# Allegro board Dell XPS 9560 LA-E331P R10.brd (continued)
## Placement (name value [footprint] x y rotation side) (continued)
PJP600  -  [JUMP_43X118]  279.59 30.74 180 bottom
PJP601  PAD-OPEN1X1M  [JUMP_43X39]  283.15 30.43 0 bottom
PJP602  PAD-OPEN 3X3M  [JUMP_43X79]  283.02 28.9 270 top
PJP603  PAD-OPEN 4X4M  [JUMP_43X118]  256.73 25.2 270 bottom
PJP700  PAD-OPEN 3X3M  [JUMP_43X79]  185.7 115.9 0 top
PJP701  PAD-OPEN 4X4M  [JUMP_43X118]  215.71 117.65 270 top
PJP702  PAD-OPEN 4X4M  [JUMP_43X118]  215.71 117.65 270 bottom
PJP800  -  [JUMP_43X118]  117.22 63.83 0 bottom
PJP900  -  [JUMP_43X118]  224.28 116.09 180 bottom
PJP1200  -  [JUMP_43X118]  129.21 107.13 90 bottom
PJP1205  PAD-OPEN1X1M  [JUMP_43X39]  307.73 21.92 180 top
PJP1206  PAD-OPEN1X1M  [JUMP_43X39]  276.28 8.64 0 top
PJP1300  -  [JUMP_43X118]  107.25 68.59 270 top
PJP1301  -  [JUMP_43X118]  109.28 98.24 90 bottom
PJP1302  PAD-OPEN 43X39  [JUMP_43X39]  103.07 17.92 180 top
PJP1303  PAD-OPEN 43X39  [JUMP_43X39]  102.95 13.6 180 top
PL104  BLM15AG102SN1D_2P  [MURAT_BLM15AG102SN1D_2P]  17.83 75.76 0 top
PL105  HCB2012KF-121T50_0805  [TAI-T_HCB2012KF-121T50_2P]  26.54 77.03 0 bottom
PL106  HCB2012KF-121T50_0805  [TAI-T_HCB2012KF-121T50_2P]  27.1 78.62 90 bottom
PL107  HCB2012KF-121T50_0805  [TAI-T_HCB2012KF-121T50_2P]  23.37 22.23 270 bottom
PL108  HCB2012KF-121T50_0805  [TAI-T_HCB2012KF-121T50_2P]  21.59 22.23 270 bottom
PL200  HCB2012KF-121T50_0805  [TAI-T_HCB2012KF-121T50_2P]  21.72 23.82 0 top
PL201  HCB2012KF-121T50_0805  [TAI-T_HCB2012KF-121T50_2P]  21.72 22.17 0 top
PL202  HCB2012KF-121T50_0805  [TAI-T_HCB2012KF-121T50_2P]  21.44 18.85 270 top
PL203  HCB2012KF-121T50_0805  [TAI-T_HCB2012KF-121T50_2P]  19.39 18.81 270 top
PL300  HCB2012KF-121T50_0805  [TAI-T_HCB2012KF-121T50_2P]  52.44 9.72 180 bottom
PL301  HCB2012KF-121T50_0805  [TAI-T_HCB2012KF-121T50_2P]  52.44 8.01 180 bottom
PL302  3.3UH_VMPI1004AR-3R3M-Z01_11A_20%  [TAI-T_VMPI1004AR-3R3M-Z01_2P]  35.99 3.97 90 bottom
PL400  3.3UH_PCMB063T-3R3MS_6.5A_20%  [CYNTE_PCMB063T-3R3MS_2P]  331.37 25.32 0 top
PL401  1.5UH_PCMC063T-1R5MN_9A_20%  [CYNTE_PCMC063T-1R5MN_2P]  336.13 6.1 180 top
PL402  HCB2012KF-121T50_0805  [TAI-T_HCB2012KF-121T50_2P]  318.26 14.42 0 top
PL403  HCB2012KF-121T50_0805  [TAI-T_HCB2012KF-121T50_2P]  318.26 16.2 0 top
PL500  HCB2012KF-121T50_0805  [TAI-T_HCB2012KF-121T50_2P]  136.83 10.61 180 bottom
PL501  1UH_PCMB053T-1R0MS_7A_20%  [CYNTE_PCMB053T-1R0MS_2P]  128.78 3.88 180 bottom
PL600  1UH_PCMB063T-1R0MS_12A_20%  [CYNTE_PCMB063T-1R0MS_2P]  262.53 31.76 0 bottom
PL601  HCB2012KF-121T50_0805  [TAI-T_HCB2012KF-121T50_2P]  279.39 27.31 180 bottom
PL700  HCB2012KF-121T50_0805  [TAI-T_HCB2012KF-121T50_2P]  185.25 118.69 0 bottom
PL701  0.47UH_MMD-06CZ-R47M-V1_17.5A_20%  [MAG_MMD-06CZ-R47M-V1_2P]  198.95 115.64 0 bottom
PL800  HCB2012KF-121T50_0805  [TAI-T_HCB2012KF-121T50_2P]  105.09 57.49 90 top
PL801  1UH_PCMB053T-1R0MS_7A_20%  [CYNTE_PCMB053T-1R0MS_2P]  112.9 60.52 90 bottom
PL900  HCB2012KF-121T50_0805  [TAI-T_HCB2012KF-121T50_2P]  246.37 114.82 180 bottom
PL901  1UH_PCMB053T-1R0MS_7A_20%  [CYNTE_PCMB053T-1R0MS_2P]  235.79 114.69 180 bottom
PL1000  HCB2012KF-121T50_0805  [TAI-T_HCB2012KF-121T50_2P]  163.32 108.51 270 bottom
PL1001  HCB2012KF-121T50_0805  [TAI-T_HCB2012KF-121T50_2P]  165.04 108.5 270 bottom
PL1002  0.22UH_MMD-06DZIR22MEM2L_32A_20%  [MAG_MMD-06DZIR22MEM2L_2P]  176.17 99.96 0 bottom
PL1003  0.22UH_MMD-06DZIR22MEM2L_32A_20%  [MAG_MMD-06DZIR22MEM2L_2P]  176.86 107.13 0 bottom
PL1200  0.22UH_MMD-06DZIR22MEM2L_32A_20%  [MAG_MMD-06DZIR22MEM2L_2P]  146.46 105.04 0 bottom
PL1201  0.22UH_MMD-06DZIR22MEM2L_32A_20%  [MAG_MMD-06DZIR22MEM2L_2P]  146.46 112.53 0 bottom
PL1202  0.22UH_MMD-06DZIR22MEM2L_32A_20%  [MAG_MMD-06DZIR22MEM2L_2P]  158.24 108.67 270 bottom
PL1203  HCB2012KF-121T50_0805  [TAI-T_HCB2012KF-121T50_2P]  134.54 106.88 90 bottom
PL1204  HCB2012KF-121T50_0805  [TAI-T_HCB2012KF-121T50_2P]  132.83 106.88 90 bottom
PL1300  0.22UH_MMD-06DZIR22MEM2L_32A_20%  [MAG_MMD-06DZIR22MEM2L_2P]  112.99 82.36 0 bottom
PL1301  0.22UH_MMD-06DZIR22MEM2L_32A_20%  [MAG_MMD-06DZIR22MEM2L_2P]  112.12 70.24 0 bottom
PL1303  HCB2012KF-121T50_0805  [TAI-T_HCB2012KF-121T50_2P]  106.62 67.06 90 bottom
PL1304  HCB2012KF-121T50_0805  [TAI-T_HCB2012KF-121T50_2P]  108.4 67.06 90 bottom
PL1305  HCB2012KF-121T50_0805  [TAI-T_HCB2012KF-121T50_2P]  105.6 97.42 270 bottom
PL1306  0.47UH_MMD05CZR47M_12A_20%  [MAG_MMD05CZR47M_4P]  108.4 88.77 0 bottom
PL1400  1UH_1239AS-H-1R0M-P2_3A_20%  [TOKO_1239AS-H-1R0M-P2_2P]  247.41 104.28 0 top
PL1444  HCB2012KF-121T50_0805  [TAI-T_HCB2012KF-121T50_2P]  248.41 112.32 270 top
PL1500  0.22UH_MMD-06DZIR22MEM2L_32A_20%  [MAG_MMD-06DZIR22MEM2L_2P]  190.63 100.18 0 bottom
PL1501  HCB2012KF-121T50_0805  [TAI-T_HCB2012KF-121T50_2P]  183.07 112.9 270 top
PL1502  HCB2012KF-121T50_0805  [TAI-T_HCB2012KF-121T50_2P]  184.79 112.9 270 top
PQ100  -  [FDV301N-G_SOT23-3]  42.74 33.98 180 top
PQ101  -  [MMBT3904WH_SOT323-3]  39.03 32.77 270 top
PQ200  -  [AON7409_DFN8-5]  20.89 27.59 90 bottom
PQ201  -  [AON7409_DFN8-5]  28.58 29.6 270 bottom
PQ204  -  [NTR4502PT1G_SOT23-3]  16.1 33.85 270 top
PQ205  S TR 2N7002KW 1N SOT323-3  [SSM3K7002FU_SC70-3]  26.17 32.58 270 top
PQ206  S TR 2N7002KW 1N SOT323-3  [SSM3K7002FU_SC70-3]  30.1 33.53 180 top
PQ208  S TR 2N7002KW 1N SOT323-3  [SSM3K7002FU_SC70-3]  22.74 28.47 270 top
PQ211  S TR 2N7002KW 1N SOT323-3  [SSM3K7002FU_SC70-3]  22.74 30.86 270 top
PQ212  -  [AON7409_DFN8-5]  13.11 29.8 0 bottom
PQ213  -  [AON7409_DFN8-5]  18.77 26.93 180 bottom
PQ214  -  [AON7409_DFN8-5]  15.54 63.28 180 bottom
PQ216  -  [NTR4502PT1G_SOT23-3]  14.48 27.15 0 top
PQ217  -  [NTR4502PT1G_SOT23-3]  20.92 7.73 270 top
PQ218  S TR 2N7002KW 1N SOT323-3  [SSM3K7002FU_SC70-3]  16.7 59.7 180 bottom
PQ219  S TR 2N7002KW 1N SOT323-3  [SSM3K7002FU_SC70-3]  25.85 4.33 270 top
PQ220  S TR 2N7002KW 1N SOT323-3  [SSM3K7002FU_SC70-3]  25.83 1.92 270 top
PQ221  -  [AO3413_SOT23-3]  36.32 24.88 0 top
PQ222  S TR 2N7002KW 1N SOT323-3  [SSM3K7002FU_SC70-3]  30.1 1.6 0 top
PQ223  S TR 2N7002KW 1N SOT323-3  [SSM3K7002FU_SC70-3]  15.69 1.66 0 top
PQ224  -  [AO3413_SOT23-3]  14.48 22.42 0 top
PQ225  S TR 2N7002KW 1N SOT323-3  [SSM3K7002FU_SC70-3]  27.75 26.08 90 top
PQ228  S TR 2N7002KW 1N SOT323-3  [SSM3K7002FU_SC70-3]  11.11 24.2 270 bottom
PQ229  S TR 2N7002KW 1N SOT323-3  [SSM3K7002FU_SC70-3]  22.99 13.79 180 top
PQ230  S TR 2N7002KW 1N SOT323-3  [SSM3K7002FU_SC70-3]  6.16 18.93 90 bottom
PQ231  S TR 2N7002KW 1N SOT323-3  [SSM3K7002FU_SC70-3]  33.4 31.5 180 top
PQ232  S TR 2N7002KW 1N SOT323-3  [SSM3K7002FU_SC70-3]  30.35 7.33 180 top
PQ233  S TR 2N7002KW 1N SOT323-3  [SSM3K7002FU_SC70-3]  20.26 13.79 180 top
PQ300  -  [SIR472DP-T1-GE3_POWERPAK8-5]  43.18 13.88 90 bottom
PQ301  -  [SIR472DP-T1-GE3_POWERPAK8-5]  42.51 8.02 90 bottom
PQ302  -  [SIRA06DP-T1-GE_POWERPAKSO-8-5]  47.68 5.98 270 bottom
PQ303  -  [AON7409_DFN8-5]  28.13 22.16 270 bottom
PQ304  S TR 2N7002KW 1N SOT323-3  [SSM3K7002FU_SC70-3]  57.42 11.11 180 bottom
PQ400  -  [MDV1528URH_PDFN33-8-5]  332.42 21.15 180 top
PQ401  -  [MDU1516URH_POWERDFN56-8-5]  326.9 10.64 0 top
PQ402  -  [MDV1524URH_PDFN33-8-5]  334.58 18.11 0 top
PQ403  -  [MDU1512RH_POWERDFN56-8-5]  337.25 15.99 180 top
PQ600  -  [AON7406L_DFN8-5]  271.19 30.91 90 bottom
PQ601  -  [AON7516_DFN8-5]  273.57 28.29 270 bottom
PQ700  -  [RJU003N03_UMT3]  198.57 110.66 0 top
PQ1300  -  [AON7934_DFN3X3A8-10]  107.13 92.46 90 bottom
PR100  0_0402_5%  [R_0402]  45.15 33.68 270 top
PR101  2.2K_0402_1%  [R_0402]  45.15 30.98 90 top
PR102  33_0402_5%  [R_0402]  18.75 74.85 180 top
PR103  100K_0402_1%  [R_0402]  40.34 34.45 180 top
PR104  10K_0402_1%  [R_0402]  40.26 31.43 90 top
PR105  15K_0402_1%  [R_0402]  38.5 34.45 180 top
PR106  100_0402_1%  [R_0402]  19.88 10.12 270 top
PR108  100_0402_1%  [R_0402]  21.27 14.09 90 top
PR111  100_0402_1%  [R_0402]  26 11.88 0 top
PR112  10K_0402_1%  [R_0402]  26.92 13.09 180 top
PR200  100K_0402_5%  [R_0402]  27.42 28.94 270 top
PR201  1M_0402_5%  [R_0402]  20.7 29.04 270 top
PR202  100K_0402_5%  [R_0402]  18.09 31.38 0 top
PR203  100K_0402_5%  [R_0402]  26.51 28.03 90 top
PR205  1M_0402_5%  [R_0402]  21.59 28.13 90 top
PR206  100K_0402_5%  [R_0402]  27.14 34.21 0 top
PR209  0_0402_5%  [R_0402]  26.61 29.78 90 top
PR213  1M_0402_5%  [R_0402]  20.63 30.22 90 top
PR217  1M_0402_5%  [R_0402]  22.43 29.92 180 top
PR219  1M_0402_5%  [R_0402]  11.75 61.08 90 top
PR220  100K_0402_5%  [R_0402]  21.48 3.3 90 top
PR222  1M_0402_5%  [R_0402]  21.48 2.47 270 top
PR223  100K_0402_5%  [R_0402]  25.08 8.71 270 top
PR224  1M_0402_5%  [R_0402]  23.13 10.17 180 top
PR225  1M_0402_5%  [R_0402]  14.78 59.32 0 bottom
PR226  100K_0402_5%  [R_0402]  20.92 5.15 0 top
PR227  0_0402_5%  [R_0402]  16.63 26.21 0 top
PR228  0_0402_5%  [R_0402]  26.67 7.45 270 top
PR229  100K_0402_5%  [R_0402]  20.08 4.07 180 top
PR230  100K_0402_5%  [R_0402]  25.08 6.93 270 top
PR231  100K_0402_1%  [R_0402]  18.3 3.5 180 top
PR232  10K_0402_1%  [R_0402]  24.08 1.81 90 top
PR234  100K_0402_5%  [R_0402]  13.13 2.42 0 top
PR235  0_0402_5%  [R_0402]  28.66 7.76 270 top
PR240  100K_0402_5%  [R_0402]  17.35 21.66 180 top
PR243  100K_0402_5%  [R_0402]  16.96 23.45 270 top
PR251  100K_0402_1%  [R_0402]  9.44 21.6 0 bottom
PR252  100K_0402_1%  [R_0402]  9.46 22.72 0 top
PR253  100K_0402_1%  [R_0402]  9.46 22.49 0 bottom
PR254  180K_0402_1%  [R_0402]  15.36 22.88 0 bottom
PR255  100K_0402_1%  [R_0402]  18.59 22.88 180 bottom
PR257  180K_0402_1%  [R_0402]  10.38 23.97 180 top
PR258  1.8M_0402_1%  [R_0402]  17.34 21.01 90 bottom
PR259  1.8M_0402_1%  [R_0402]  11.81 22.75 270 top
PR260  130K_0402_1%  [R_0402]  19.51 19.06 180 bottom
PR261  140K_0402_1%  [R_0402]  9.4 18.61 0 bottom
PR263  16.5K_0402_1%  [R_0402]  10.33 21.85 180 top
PR264  200K_0402_1%  [R_0402]  9.46 24.85 0 top
PR265  200K_0402_1%  [R_0402]  13.53 22.88 0 bottom
PR267  0_0402_5%  [R_0402]  24.07 4.66 270 top
PR268  0_0402_5%  [R_0402]  30.81 29.33 90 top
PR270  1M_0402_5%  [R_0402]  11.23 3.82 0 top
PR271  300K_0402_5%  [R_0402]  28.31 24.58 0 top
PR272  300K_0402_5%  [R_0402]  28.31 23.69 0 top
PR273  16.5K_0402_1%  [R_0402]  17.65 20.07 0 bottom
PR275  100K_0402_1%  [R_0402]  34.28 31.94 0 top
PR276  2K_0402_1%  [R_0402]  35.15 33.78 180 top
PR277  0_0402_5%  [R_0402]  31.75 31.39 270 top
PR278  100K_0402_1%  [R_0402]  18.61 11.87 90 top
PR279  0_0402_5%  [R_0402]  19.24 14.09 90 top
PR281  0_0402_5%  [R_0402]  12 23.75 90 top
PR282  100K_0402_5%  [R_0402]  13.13 1.53 0 top
PR283  100K_0402_5%  [R_0402]  9.08 2.16 90 top
PR290  0_0402_5%  [R_0402]  8.45 11.17 90 bottom
PR300  0.01_1206_1%  [R_1206_4P-D]  55.02 8.26 270 bottom
PR301  0_0402_5%  [R_0402]  52.57 11.1 90 top
PR302  0_0402_5%  [R_0402]  51.69 11.1 90 top
PR303  4.02K_0402_1%  [R_0402]  54.17 11.76 90 top
PR304  10_1206_5%  [R_1206]  51.12 15.06 270 bottom
PR305  294K_0402_1%  [R_0402]  55.77 12.67 270 bottom
PR306  0_0402_5%  [R0402_0OHM]  60.26 17.48 180 top
PR307  2.2_0603_5%  [R_0603]  50.8 17.53 180 top
PR308  59K_0402_1%  [R_0402]  55.88 14.28 90 bottom
PR309  0_0402_5%  [R0402_0OHM]  60.26 18.37 180 top
PR310  0.005_2512_1%  [RL-3264-9W-R005-FNH_2512_2512]  38.33 23.02 90 bottom
PR311  100K_0402_1%  [R_0402]  54.9 11.76 90 bottom
PR312  0_0402_5%  [R0402_0OHM]  54.04 11.76 90 bottom
PR313  4.7_1206_5%  [R_1206]  32.58 3.88 90 top
PR314  0_0402_5%  [R0402_0OHM]  56.9 11.76 90 top
PR315  100_0402_1%  [R_0402]  60.26 16.52 180 top
PR316  150K_0402_1%  [R_0402]  55.12 12.65 270 top
PR317  0_0402_5%  [R0402_0OHM]  60.28 14.74 180 top
PR318  10K_0402_1%  [R_0402]  52.39 21.34 90 top
PR319  4.02K_0402_1%  [R_0402]  55.18 21.22 90 top
PR320  10_0603_1%  [R_0603]  56.26 21.22 90 bottom
PR321  1K_0402_1%  [R_0402]  57.34 22.42 270 top
PR322  0_0402_5%  [R0402_0OHM]  58.23 22.42 270 top
PR323  121K_0402_1%  [R_0402]  56.83 19.45 270 bottom
PR324  0_0402_5%  [R0402_0OHM]  60.28 15.63 180 top
PR325  10K_0402_1%  [R_0402]  57.8 16.52 180 bottom
PR326  2.2K_0402_5%  [R_0402]  346.97 26.3 270 top
PR327  100K_0402_5%  [R_0402]  58.93 10.63 270 bottom
PR399  0_0402_5%  [R_0402]  52.77 11.74 90 bottom
PR400  0_0402_5%  [R0402_0OHM]  348.88 21.98 180 bottom
PR401  68.1K_0402_1%  [R_0402]  348.87 22.87 180 top
PR402  160K_0402_1%  [R_0402]  348.03 18.93 0 top
PR403  100K_0402_1%  [R_0402]  348.87 21.98 180 top
PR404  102K_0402_1%  [R_0402]  348.03 19.82 0 top
PR405  16.9K_0402_1%  [R_0402]  346.97 24.41 270 top
PR406  10.2K_0402_1%  [R_0402]  348.03 18.04 0 top
PR407  0_0402_5%  [R0402_0OHM]  345.12 24.41 270 top
PR408  0_0402_5%  [R0402_0OHM]  346.08 24.41 270 top
PR409  0_0402_5%  [R0402_0OHM]  347.98 17.14 90 bottom
PR410  200_0402_1%  [R_0402]  348.03 17.09 0 top
PR411  2.2_0603_5%  [R_0603]  342.27 24.08 0 top
PR412  2.2_0603_5%  [R_0603]  341.89 17.22 0 top
PR413  4.7_1206_5%  [R_1206]  337.25 31.17 180 top
PR414  4.7_1206_5%  [R_1206]  339.28 10.68 90 top
PR415  0_0402_5%  [R0402_0OHM]  340.58 21.97 180 top
PR428  100K_0402_1%  [R_0402]  345.12 24.41 270 bottom
PR500  0_0402_5%  [R0402_0OHM]  131.03 3.2 270 bottom
PR501  1M_0402_1%  [R_0402]  130.68 3.18 270 top
PR502  4.7_1206_5%  [R_1206]  126.68 8.33 0 bottom
PR503  0_0603_5%  [R_0603]  134.88 7.69 180 top
PR504  90.9K_0402_1%  [R_0402]  134.76 2.16 90 top
PR508  133K_0402_1%  [R_0402]  135.68 3.06 270 top
PR510  0_0402_5%  [R_0402]  132.46 2.26 90 top
PR512  0_0402_5%  [R_0402]  133.33 2.97 270 bottom
PR600  2.2_0603_5%  [R_0603]  283.15 28.65 0 bottom
PR601  3.57K_0402_1%  [R_0402]  288.99 26.49 180 bottom
PR602  4.7_1206_5%  [R_1206]  269.43 26.87 180 bottom
PR603  5.1_0603_5%  [R_0603]  289.54 25.23 90 top
PR604  16.2K_0402_1%  [R_0402]  291.85 31.19 90 top
PR605  1M_0402_1%  [R_0402]  292.75 27.19 180 bottom
PR606  0_0402_5%  [R0402_0OHM]  292.75 28.46 180 bottom
PR607  27K_0402_1%  [R_0402]  292.8 31.19 90 bottom
PR608  0_0402_5%  [R0402_0OHM]  292.75 29.35 180 bottom
PR609  100K_0402_5%  [R_0402]  291.92 27 180 top
PR610  0_0402_5%  [R_0402]  291.83 30.23 0 top
PR700  0_0402_5%  [R0402_0OHM]  187.17 118.53 0 top
PR701  187K_0402_1%  [R_0402]  191.52 118.96 270 bottom
PR702  107K_0402_1%  [R_0402]  190.56 118.96 270 bottom
PR703  200K_0402_1%  [R_0402]  189.61 118.96 270 bottom
PR704  19.1K_0402_1%  [R_0402]  194.31 118.94 270 bottom
PR705  10_1206_5%  [R_1206]  195.26 115.58 0 top
PR706  0_0402_5%  [R0402_0OHM]  194.88 118.96 270 top
PR707  100K_0402_1%  [R_0402]  196.85 118.97 270 top
PR708  2_0603_5%  [R_0603]  196.72 113.99 270 top
PR722  23.2K_0402_1%  [R_0402]  193.36 118.94 270 bottom
PR724  95.3K_0402_1%  [R_0402]  196.79 110.83 270 top
PR725  100K_0402_5%  [R_0402]  199.4 107.9 180 top
PR728  0_0402_5%  [R0402_0OHM]  199.4 106.88 180 top
PR729  10_0402_1%  [R_0402]  192.28 118.96 270 top
PR730  0_0402_5%  [R0402_0OHM]  193.36 118.04 90 top
PR755  2.7K_0402_1%  [R_0402]  197.89 117.04 0 top
PR800  0_0402_5%  [R0402_0OHM]  109.92 64.51 90 bottom
PR801  1M_0402_1%  [R_0402]  109.03 64.51 90 bottom
PR802  4.7_1206_5%  [R_1206]  114.17 57.67 180 bottom
PR803  0_0603_5%  [R_0603]  107.19 62.11 270 top
PR804  36.5K_0402_1%  [R_0402]  107.13 64.51 90 bottom
PR806  62K_0402_1%  [R_0402]  105.28 64.51 90 top
PR808  0_0402_5%  [R_0402]  171.69 70.68 270 top
PR809  0_0402_5%  [R_0402]  170.74 70.68 270 top
PR810  100_0402_1%  [R_0402]  170.74 72.46 270 top
PR811  0_0402_5%  [R_0402]  108.08 65.43 270 bottom
PR812  0_0402_5%  [R_0402]  107.13 64.51 90 top
PR813  100_0402_1%  [R_0402]  171.69 72.46 270 top
PR902  1M_0402_1%  [R_0402]  240.48 110.55 90 top
PR903  4.7_1206_5%  [R_1206]  232.67 115.01 0 top
PR904  0_0603_5%  [R_0603]  241.68 114.25 180 top
PR905  100K_0402_1%  [R_0402]  245.3 110.17 180 bottom
PR906  10K_0402_5%  [R_0402]  241.36 110.55 90 bottom
PR907  133K_0402_1%  [R_0402]  243.14 111.46 270 bottom
PR908  0_0402_5%  [R_0402]  241.36 110.55 90 top
PR909  0_0402_5%  [R_0402]  242.25 110.56 90 top
PR910  0_0402_5%  [R_0402]  242.25 111.46 270 bottom
PR986  0_0402_5%  [R_0402]  241.38 109.29 180 top
PR987  0_0402_5%  [R_0402]  241.38 108.42 180 top
PR988  62K_0402_1%  [R_0402]  241.38 107.54 180 top
PR1000  10K_0402_1%  [R_0402]  163.95 116.4 0 bottom
PR1001  22.6K_0402_1%  [R_0402]  165.18 115.39 180 bottom
PR1002  169K_0402_1%  [R_0402]  166.55 115.51 0 top
PR1003  0_0402_5%  [R0402_0OHM]  163.91 117.41 0 bottom
PR1004  2.2K_0402_5%  [R_0402]  165.18 114.44 180 bottom
PR1005  20.5K_0402_1%  [R_0402]  167.39 117.99 90 top
PR1006  4.32K_0402_1%  [R_0402]  167.32 118.06 90 bottom
PR1007  6.19K_0402_1%  [R_0402]  166.37 118.97 270 bottom
PR1008  16.5K_0402_1%  [R_0402]  168.59 117.87 90 bottom
PR1009  10_1206_5%  [R_1206]  176.98 98.62 180 top
PR1010  2.2_0603_5%  [R_0603]  164.58 112.47 180 bottom
PR1011  309_0402_1%  [R_0402]  172.2 115.32 0 bottom
PR1012  2.2_0603_5%  [R_0603]  167.53 110.75 180 bottom
PR1013  412K_0402_1%  [R_0402]  170.5 118.91 270 bottom
PR1014  20_0402_1%  [R_0402]  171.45 117.99 90 bottom
PR1015  2.2_0603_5%  [R_0603]  171.65 112.03 0 bottom
PR1016  100_0402_1%  [R_0402]  173.61 110.87 0 top
PR1017  0_0402_5%  [R0402_0OHM]  171.71 114.05 0 top
PR1018  0_0402_5%  [R0402_0OHM]  170.32 115.71 180 top
PR1019  10K_0402_5%  [R_0402]  172.19 113.55 0 bottom
PR1020  10_1206_5%  [R_1206]  177 106.37 180 top
PR1021  0_0402_5%  [R0402_0OHM]  172.1 116.15 180 top
PR1022  82K_0402_1%  [R_0402]  172.2 114.44 0 bottom
PR1023  100_0402_1%  [R_0402]  178.64 110.89 180 top
PR1100  12.1K_0402_1%  [R_0402]  111.13 109.99 0 bottom
PR1101  1_0402_5%  [R_0402]  117.54 112.09 270 bottom
PR1102  0_0402_5%  [R0402_0OHM]  118.43 112.09 270 bottom
PR1103  100_0402_1%  [R_0402]  116.8 108.82 180 bottom
PR1104  95.3K_0402_1%  [R_0402]  111.13 109.04 0 bottom
PR1105  10.2K_0402_1%  [R_0402]  111.13 108.09 0 top
PR1106  27.4K_0402_1%  [R_0402]  108.78 107.2 0 bottom
PR1107  165K_0402_1%  [R_0402]  122.44 111.2 90 top
PR1108  16.9K_0402_1%  [R_0402]  121.55 111.2 90 top
PR1109  5.62K_0402_1%  [R_0402]  120.59 111.2 90 top
PR1110  110K_0402_1%  [R_0402]  119.7 111.2 90 top
PR1111  3.6K_0402_1%  [R_0402]  111.13 107.13 0 bottom
PR1112  1K_0402_1%  [R_0402]  108.83 106.24 0 top
PR1113  2.94K_0402_1%  [R_0402]  109.73 104.47 90 top
PR1114  1.91K_0402_1%  [R_0402]  113.92 112.09 270 top
PR1115  1.1K_0402_1%  [R_0402]  122.56 108.91 0 top
PR1116  48.7K_0402_1%  [R_0402]  123.31 110.82 0 top
PR1117  1K_0402_1%  [R_0402]  124.84 108.9 90 top
PR1118  0_0402_5%  [R0402_0OHM]  111.99 112.09 270 top
PR1119  0_0402_5%  [R0402_0OHM]  112.97 112.09 270 top
PR1120  11K_0402_1%  [R_0402]  123.41 109.91 180 bottom
PR1121  2.61K_0402_1%  [R_0402]  114.07 93.05 0 bottom
PR1122  2.61K_0402_1%  [R_0402]  120.31 86.43 0 bottom
PR1123  11K_0402_1%  [R_0402]  112.04 103.01 180 bottom
PR1124  2K_0402_1%  [R_0402]  123.05 107.13 0 top
PR1125  1K_0402_1%  [R_0402]  125.1 105.37 270 bottom
PR1126  4.42K_0402_1%  [R_0402]  122.56 105.29 0 bottom
PR1127  1K_0402_1%  [R_0402]  109.73 104.45 90 bottom
PR1128  2.49K_0402_1%  [R_0402]  122.56 106.24 0 bottom
PR1129  102K_0402_1%  [R_0402]  122.56 104.28 0 top
PR1130  412_0402_1%  [R_0402]  111.13 105.29 0 bottom
PR1131  45.3_0402_1%  [R_0402]  114.81 114 270 top
PR1132  0_0402_5%  [R0402_0OHM]  115.76 112.1 270 top
PR1133  357_0402_1%  [R_0402]  118.49 100.47 270 bottom
PR1134  11K_0402_1%  [R_0402]  119.86 98.28 270 bottom
PR1135  1K_0402_1%  [R_0402]  118.11 97.24 90 bottom
PR1136  2.61K_0402_1%  [R_0402]  150.11 99.89 180 bottom
PR1137  90.9K_0402_1%  [R_0402]  112.9 100.47 270 top
PR1138  27.4K_0402_1%  [R_0402]  113.67 98.69 0 top
PR1139  2K_0402_1%  [R_0402]  116.59 100.47 270 top
PR1140  1K_0402_1%  [R_0402]  117.48 100.45 270 bottom
PR1141  2.26K_0402_1%  [R_0402]  115.7 100.47 270 bottom
PR1142  2.43K_0402_1%  [R_0402]  116.59 99.55 90 bottom
PR1143  2K_0402_1%  [R_0402]  109.55 107.2 180 top
PR1144  10.2K_0402_1%  [R_0402]  114.75 99.55 90 top
PR1145  100_0402_1%  [R_0402]  116.65 114 270 top
PR1200  10_1206_5%  [R_1206]  147.77 103.39 270 top
PR1201  100K_0402_1%  [R_0402]  128.27 99.77 180 bottom
PR1202  3.65K_0603_1%  [R_0603]  129.2 99.25 0 bottom
PR1203  2.2_0402_1%  [R_0402]  127.38 98.81 0 bottom
PR1204  10_1206_5%  [R_1206]  145.23 117.29 0 bottom
PR1205  100K_0402_1%  [R_0402]  128.27 101.93 180 bottom
PR1206  3.65K_0603_1%  [R_0603]  129.2 100.5 0 bottom
PR1207  2.2_0402_1%  [R_0402]  127.38 100.97 0 bottom
PR1208  10_1206_5%  [R_1206]  160.78 107.32 90 top
PR1209  100K_0402_1%  [R_0402]  128.08 97.74 180 bottom
PR1210  3.65K_0603_1%  [R_0603]  128.98 97 0 bottom
PR1211  2.2_0402_1%  [R_0402]  127.15 96.83 0 bottom
PR1212  100K_0402_1%  [R_0402]  125.73 99.77 180 bottom
PR1213  100K_0402_1%  [R_0402]  125.73 98.81 180 bottom
PR1214  100K_0402_1%  [R_0402]  125.73 101.67 180 bottom
PR1215  100K_0402_1%  [R_0402]  125.73 100.72 180 bottom
PR1216  100K_0402_1%  [R_0402]  125.68 96.66 180 bottom
PR1217  100K_0402_1%  [R_0402]  125.67 97.54 180 bottom
PR1218  0_0402_5%  [R0402_0OHM-NPM]  147.45 105.04 0 bottom
PR1219  0_0402_5%  [R0402_0OHM-NPM]  151.51 105.04 180 bottom
PR1220  0_0402_5%  [R0402_0OHM-NPM]  147.45 112.59 0 bottom
PR1221  0_0402_5%  [R0402_0OHM-NPM]  151.51 112.59 180 bottom
PR1222  0_0402_5%  [R0402_0OHM-NPM]  158.18 107.64 270 bottom
PR1223  0_0402_5%  [R0402_0OHM-NPM]  158.18 103.64 90 bottom
PR1224  2.2_0402_1%  [R_0402]  137.54 109.88 270 bottom
PR1225  2.2_0402_1%  [R_0402]  137.67 115.71 270 bottom
PR1226  2.2_0402_1%  [R_0402]  157.43 118.88 180 bottom
PR1300  4.7_1206_5%  [R_1206]  111.63 81.29 270 top
PR1301  3.65K_0603_1%  [R_0603]  105.92 101.99 90 top
PR1302  2.2_0402_1%  [R_0402]  109.22 102.83 270 top
PR1303  100K_0402_1%  [R_0402]  105.98 102.18 90 bottom
PR1304  2.2_0402_1%  [R_0402]  108.27 101.91 90 top
PR1305  3.65K_0603_1%  [R_0603]  107.19 101.99 90 top
PR1306  100K_0402_1%  [R_0402]  107.19 102.18 90 bottom
PR1307  4.7_1206_5%  [R_1206]  112.02 69.41 90 top
PR1308  4.7_1206_5%  [R_1206]  105.54 87.7 90 bottom
PR1309  3.65K_0603_1%  [R_0603]  126.62 104.21 90 top
PR1311  0_0402_5%  [R_0402]  115.46 95.51 90 top
PR1312  0_0402_5%  [R0402_0OHM-NPM]  114 82.48 0 bottom
PR1313  0_0402_5%  [R0402_0OHM-NPM]  118.06 82.48 180 bottom
PR1314  0_0402_5%  [R0402_0OHM-NPM]  113.11 70.24 0 bottom
PR1315  0_0402_5%  [R0402_0OHM-NPM]  117.18 70.24 180 bottom
PR1318  10_0402_1%  [R_0402]  116.65 112.1 270 top
PR1319  49.9_0402_1%  [R_0402]  114.81 112.1 270 top
PR1320  2.2_0402_1%  [R_0402]  103.93 81.49 270 bottom
PR1321  2.2_0402_1%  [R_0402]  103.63 77.26 270 bottom
PR1400  100K_0402_5%  [R_0402]  245.95 109.23 180 bottom
PR1401  4.7_0603_5%  [R_0603]  247.65 104.85 0 bottom
PR1402  20K_0402_1%  [R_0402]  243.07 108.34 0 bottom
PR1403  0_0402_5%  [R_0402]  244.08 103.7 0 bottom
PR1404  1M_0402_1%  [R_0402]  245 102.75 180 bottom
PR1405  10K_0402_1%  [R_0402]  244.03 107.4 270 bottom
PR1500  10K_0402_1%  [R_0402]  178.25 111.81 0 top
PR1501  0_0402_5%  [R_0402]  177.86 111.99 270 bottom
PR1502  8.2K_0402_1%  [R_0402]  178.82 111.99 270 bottom
PR1503  0_0402_5%  [R0402_0OHM]  176.65 113.42 0 bottom
PR1505  20.5K_0402_1%  [R_0402]  177.31 114.88 180 top
PR1507  6.19K_0402_1%  [R_0402]  176.65 114.31 0 bottom
PR1508  4.32K_0402_1%  [R_0402]  176.3 116.91 0 top
PR1509  16.5K_0402_1%  [R_0402]  176.32 117.86 0 bottom
PR1510  2.2_0603_5%  [R_0603]  181.8 111.45 0 bottom
PR1511  309_0402_1%  [R_0402]  177.2 116.91 180 bottom
PR1512  10_1206_5%  [R_1206]  190.18 101.42 90 top
PR1513  2.2_0603_5%  [R_0603]  182.31 118.63 0 bottom
PR1514  20_0402_1%  [R_0402]  175.22 118.45 270 bottom
PR1515  412K_0402_1%  [R_0402]  176.32 118.82 0 bottom
PR1516  100_0402_1%  [R_0402]  175.99 119.13 0 top
PR1517  0_0402_5%  [R0402_0OHM]  206.57 55.52 270 bottom
PR1518  0_0402_5%  [R0402_0OHM]  181.11 119.45 0 top
PR1519  33K_0402_1%  [R_0402]  180.18 118.75 180 bottom
PR1520  0_0402_5%  [R0402_0OHM]  207.52 55.52 270 bottom
PR1521  100_0402_1%  [R_0402]  176.01 118.12 0 top
PR1800  100K_0402_1%  [R_0402]  178.86 14.2 180 top
PR1801  0_0402_5%  [R0402_0OHM]  178.8 8.82 90 top
PR1803  21.5K_0402_1%  [R_0402]  180.75 15.22 180 top
PR1804  10K_0402_1%  [R_0402]  178.94 16.11 270 top
PR1805  0.01_0603_1%  [R_0603]  181.37 17.22 180 top
PU202  -  [LM393DMR2G_MICRO8]  16.07 21.6 270 bottom
PU203  -  [RT9069-33GB_SOT23-5]  28.63 20.34 90 top
PU204  -  [MC74VHC1G08DFT2G_SC70-5]  10.1 2.75 270 top
PU300  BQ24777ARUYR_WQFN28_4X4  [BQ24777RUYR_WQFN28_4X4]  53.91 15.06 90 top
PU400  -  [TPS51285BRUKR_QFN20_3X3]  345.95 19.5 180 top
PU500  -  [SYX196DQNC_QFN10_3X3]  131.53 4.5 0 bottom
PU600  -  [G5616ARZ1U_TQFN20_3X3]  287.47 31.12 0 bottom
PU700  -  [TPS53353DQPR_QFN22_5X6]  195.22 116.43 270 bottom
PU800  -  [SYX196DQNC_QFN10_3X3]  109.41 62.75 180 bottom
PU900  -  [SYX196DQNC_QFN10_3X3]  239.35 113.34 0 bottom
PU1000  -  [CSD86360Q5D_SON8-7]  167.93 99.73 90 bottom
PU1001  -  [RT8816AGQW_WQFN20_3X3]  166.66 113.64 90 bottom
PU1002  -  [CSD86360Q5D_SON8-7]  168.69 105.48 90 bottom
PU1100  -  [ISL95829AHRTZ-T_TQFN48_6X6]  114.17 108.09 0 top
PU1200  -  [AOZ5029QI_QFN24_5X3P5]  138.84 108.78 90 bottom
PU1201  -  [AOZ5029QI_QFN24_5X3P5]  138.9 114.4 90 bottom
PU1202  -  [AOZ5029QI_QFN24_5X3P5]  156.16 117.46 0 bottom
PU1300  -  [AOZ5029QI_QFN24_5X3P5]  105.35 80.08 90 bottom
PU1301  -  [AOZ5029QI_QFN24_5X3P5]  104.59 72.46 90 bottom
PU1302  -  [ISL95808HRZ-TS2378_DFN8_2X2]  115.73 95.45 270 bottom
PU1400  G5719CRC1U_TDFN8_2X2  [G5719CRC1U_TDFN8_2X2-S]  245.17 107.2 0 bottom
PU1501  -  [RT8816AGQW_WQFN20_3X3]  181.72 113.85 180 bottom
PU1502  -  [CSD86360Q5D_SON8-7]  188.41 109.83 0 bottom
PU1800  -  [RT9059GQW_WDFN10_3X3]  182.03 13.87 180 top
QE2  -  [DMN65D8LDW-7_SOT363-6]  196.22 10.83 0 top
QE4  -  [DMN65D8LDW-7_SOT363-6]  311.67 16.07 180 top
QE5  MMBT3904WH_SOT323-3  [MMBT3904WH_SOT323-3-S]  173.6 119.53 180 bottom
QE6  -  [MMBT3904WH_SOT323-3]  181.03 77.57 0 top
QE7  -  [MMBT3904WH_SOT323-3]  112.56 111.41 270 bottom
QE8  -  [MMBT3904WH_SOT323-3]  179.2 48.64 180 bottom
QE9  -  [MMBT3904WH_SOT323-3]  241.11 107.37 0 bottom
QE10  -  [MMBT3904WH_SOT323-3]  308.95 19.44 90 top
QE11  -  [MMBT3904WH_SOT323-3]  27.18 54.06 0 top
QE12  -  [MMBT3904WH_SOT323-3]  281.43 28.11 180 bottom
QE13  -  [L2N7002WT1G_SC-70-3]  188.55 7.2 180 top
QE15  -  [MMBT3904WH_SOT323-3]  158.67 69.33 180 top
QE18  -  [DMN65D8LDW-7_SOT363-6]  68.34 17.6 180 bottom
QE19  -  [DMN65D8LDW-7_SOT363-6]  193.23 10.95 0 top
QF1  -  [DMN65D8LDW-7_SOT363-6]  234 43.71 270 top
QH4  -  [DMN65D8LDW-7_SOT363-6]  72.2 6.37 270 top
QI10  -  [L2N7002WT1G_SC-70-3]  317.22 39.42 180 top
QR1  -  [L2N7002WT1G_SC-70-3]  332.61 43.32 90 bottom
QR104  -  [L2N7002WT1G_SC-70-3]  272.86 6.36 180 top
QT11  2N7002KW_SOT323-3  [SSM3K7002FU_SC70-3]  27.75 96.72 180 bottom
QT12  2N7002KW_SOT323-3  [SSM3K7002FU_SC70-3]  18.61 51.19 0 bottom
QT20  -  [DMN65D8LDW-7_SOT363-6]  25.67 97.29 180 bottom
QV3  -  [DMN65D8LDW-7_SOT363-6]  249.1 46.49 0 top
QV9  -  [L2N7002WT1G_SC-70-3]  56.9 27.06 0 top
QV11  SI3457BDV-T1-E3_TSOP6~D  [SI3457BDV-T1-E3_TSOP6]  50.24 25.2 270 bottom
QV12  -  [L2N7002WT1G_SC-70-3]  52.45 22.11 0 bottom
QV13  -  [L2N7002WT1G_SC-70-3]  22.79 77.99 270 top
QV14  -  [L2N7002WT1G_SC-70-3]  18.21 92.32 180 bottom
QV21  -  [DMN63D8LDW-7_SOT363-6]  200.8 45.85 180 top
QV86  -  [DMG2301U-7_SOT23-3]  245.17 100.11 180 top
QV87  -  [L2N7002WT1G_SC-70-3]  241.9 100.51 180 top
QV89  -  [L2N7002WT1G_SC-70-3]  27.94 55.38 180 top
QV91  BSS138W 1N SOT-323-3  [2N7002W-T-R7_SOT323-3]  216.65 42.72 270 top
QV95  2N7002W-T/R7_SOT323-3  [2N7002W-T-R7_SOT323-3]  222.09 105.66 180 top
QV96  2N7002W-T/R7_SOT323-3  [2N7002W-T-R7_SOT323-3]  244.74 94.89 90 top
QV98  BSS138W 1N SOT-323-3  [2N7002W-T-R7_SOT323-3]  244.06 49.05 180 top
QV101  BSS138W 1N SOT-323-3  [2N7002W-T-R7_SOT323-3]  220.13 106.74 90 top
QV102  BSS138W 1N SOT-323-3  [2N7002W-T-R7_SOT323-3]  244.73 92.08 90 top
QV103  BSS138W 1N SOT-323-3  [2N7002W-T-R7_SOT323-3]  197.5 50.45 270 top
QV104  DMN63D8LDW-7 2N SOT363-6  [DMN65D8LDW-7_SOT363-6]  224.05 43.83 0 top
QX1  -  [DMN65D8LDW-7_SOT363-6]  21.09 94.1 90 bottom
QZ6  -  [DMN65D8LDW-7_SOT363-6]  251.32 53.03 0 top
QZ7  -  [DMN65D8LDW-7_SOT363-6]  254.05 43 0 top
QZ9  -  [DMG2301U-7_SOT23-3]  41.7 24.56 90 top
QZ14  DMN63D8LDW-7 2N SOT363-6  [DMN65D8LDW-7_SOT363-6]  223.19 117.74 90 top
QZ15  DMN63D8LDW-7 2N SOT363-6  [DMN65D8LDW-7_SOT363-6]  165.08 118.81 180 top
QZ16  DMN63D8LDW-7 2N SOT363-6  [DMN65D8LDW-7_SOT363-6]  155.2 119.84 270 top
QZ17  DMN63D8LDW-7 2N SOT363-6  [DMN65D8LDW-7_SOT363-6]  250.35 43.24 270 top
QZ18  -  [L2N7002WT1G_SC-70-3]  219.62 114.58 180 top
R1054  0_0402  [R_0402]  224.54 8.06 90 bottom
RA2  0_0603_5%  [R_0603]  3.13 30.46 90 top
RA4  200K_0201_1%  [R_0201]  2.82 28.06 180 top
RA6  33_0201_5%  [R_0201]  2.41 29.56 90 bottom
RA7  200K_0201_1%  [R_0201]  2.82 27.48 180 top
RA12  10K_0201_5%  [R_0201]  15.72 36.27 180 bottom
RA13  100K_0201_1%  [R_0201]  7.07 32.74 0 bottom
RA14  200K_0201_1%  [R_0201]  7.07 33.37 0 bottom
RA15  100K_0201_1%  [R_0201]  11.18 32.66 90 bottom
RA16  100K_0201_1%  [R_0201]  10.1 32.61 90 bottom
RA17  4.7K_0201_5%  [R_0201]  4.04 28.55 90 bottom
RA18  0_0603_5%  [R_0603]  6.76 32.87 90 top
RA19  2.2K_0402_5%~D  [R_0402]  9.98 44.9 180 top
RA20  2.2K_0402_5%~D  [R_0402]  14.12 58.54 270 top
RA21  2.2K_0402_5%~D  [R_0402]  13.23 58.54 270 top
RA27  4.7K_0402_5%~D  [R_0402]  12.59 41.47 180 top
RA28  4.7K_0402_5%~D  [R_0402]  13.6 44.9 180 top
RA29  4.7K_0402_5%~D  [R_0402]  11.43 43.27 270 top
RA30  1K_0402_5%~D  [R_0402]  10.1 43.27 270 top
RA31  1K_0402_5%~D  [R_0402]  9.93 41.47 0 top
RA51  2.4_0402_5%  [R_0402]  14.16 48.93 0 top
RA52  2.4_0402_5%  [R_0402]  13.89 52.27 0 top
RA57  10K_0201_5%  [R_0201]  2.24 28.63 0 top
RA68  10K_0201_5%  [R_0201]  13.89 36.73 315 bottom
RA73  0_0402_5%  [R_0402]  8.13 59.65 270 bottom
RA74  0_0603_5%  [R_0603]  12.17 40.57 270 top
RA75  4.7K_0402_5%~D  [R_0402]  10.91 44.9 0 top
RA77  10K_0201_5%  [R_0201]  4.55 10.58 180 bottom
RA78  0_0603_5%  [R0603_0OHM]  3.62 17.18 0 bottom
RA79  16K_0402_5%  [R_0402]  5.79 16.04 180 bottom
RA80  20K_0402_1%  [R_0402]  4.01 16.04 180 bottom
RA82  100K_0201_5%  [R_0201]  4.97 44.75 180 bottom
RA83  0_0603_5%  [R0603_0OHM]  8.09 9.03 90 top
RA84  0_0603_5%  [R0603_0OHM]  10.88 9.03 90 top
RA93  0_0402_5%~D  [R_0402]  4.19 29.9 90 bottom
RA94  0_0402_5%  [R_0402]  2.41 31.17 90 bottom
RA95  0_0402_5%  [R_0402]  3.11 59.25 270 top
RA96  33_0201_5%  [R_0201]  102.53 27.44 180 top
RA97  33_0201_5%  [R_0201]  102.61 25.14 180 top
RA98  33_0201_5%  [R_0201]  21.28 32.35 270 bottom
RA99  33_0201_5%  [R_0201]  26.49 33.29 270 bottom
RA100  0_0402_5%  [R_0402]  7.85 32.36 90 top
RA101  0_0402_5%  [R_0402]  9.75 32.78 180 top
RD1  0_0402_5%  [R_0402]  171.84 18.78 0 top
RD2  0_0402_5%  [R_0402]  173.6 24.17 0 top
RD3  0_0402_5%  [R_0402]  152.08 18.56 270 top
RD4  0_0402_5%  [R_0402]  248.51 18.44 270 top
RD5  0_0402_5%  [R0402_0OHM]  249.77 24.22 270 top
RD6  0_0402_5%  [R_0402]  228.38 18.56 270 top
RD7  10K_0402_5%  [R_0402]  268.43 13.34 180 top
RD8  10K_0402_5%  [R_0402]  267.51 9.28 0 top
RD9  0_0402_5%  [R_0402]  268.43 6.36 180 top
RD10  10K_0402_5%  [R_0402]  256.27 3.82 0 bottom
RD28  0_0402_5%  [R0402_0OHM]  172.76 17.89 180 top
RD29  0_0402_5%  [R0402_0OHM]  176.12 23.22 0 top
RD30  0_0402_5%  [R0402_0OHM]  151.19 17.65 90 top
RD31  0_0402_5%  [R0402_0OHM]  134.18 17.81 90 top
RD35  470_0402_1%  [R_0402]  132.34 17.81 90 top
RD38  0_0402_5%  [R0402_0OHM]  247.62 17.52 90 top
RD39  0_0402_5%  [R_0402]  250.66 23.31 90 top
RD40  0_0402_5%  [R0402_0OHM]  227.49 17.65 90 top
RD58  0_0402_5%  [R0402_0OHM]  254.5 3.82 0 bottom
RD59  0_0402_5%  [R_0402]  267.51 8.33 0 top
RD100  0_0402_5%  [R_0402]  233.83 8.5 0 top
RE3  300_0402_5%  [R_0402]  329.38 107.5 90 top
RE7  2.4K_0402_5%  [R_0402]  191.66 11.06 180 top
RE9  2.4K_0402_5%  [R_0402]  191.67 10.09 180 top
RE11  33_0402_5%  [R_0402]  150.19 7.71 90 top
RE13  10K_0402_5%  [R_0402]  158.29 7.95 0 top
RE14  4.7K_0402_5%  [R_0402]  159.21 6.93 180 top
RE15  47K_0402_5%  [R_0402]  348.95 117.61 180 top
RE16  0_0402_5%  [R0402_0OHM]  290.32 11.87 90 top
RE17  2.2K_0402_5%  [R_0402]  290.25 16.77 0 top
RE18  2.2K_0402_5%  [R_0402]  290.25 15.88 0 top
RE19  10K_0402_5%  [R_0402]  300.86 3.82 0 top
RE20  2.2K_0402_5%  [R_0402]  295.72 7.45 270 top
RE21  2.2K_0402_5%  [R_0402]  294.64 4.19 90 top
RE22  10K_0402_5%  [R_0402]  294.9 23.3 90 top
RE23  10K_0402_5%  [R_0402]  290.22 21.03 270 top
RE24  4.7K_0402_5%  [R_0402]  301.88 24.22 270 top
RE25  10K_0402_5%  [R_0402]  294.82 7.45 270 top
RE26  4.7K_0402_5%  [R_0402]  300.99 24.22 270 top
RE27  10K_0402_5%  [R_0402]  299.39 28.08 0 top
RE30  100K_0402_5%  [R_0402]  298.45 5.04 270 top
RE31  10K_0402_5%  [R_0402]  310.44 17.66 0 top
RE32  100K_0402_5%  [R_0402]  300.99 26.5 270 top
RE33  10K_0402_5%  [R_0402]  301.88 26.5 270 top
RE34  100K_0402_5%  [R_0402]  291.72 4.12 90 top
RE35  0_0402_5%  [R_0402]  303.28 24.22 270 top
RE36  1K_0402_5%  [R_0402]  283.97 3.74 90 top
RE37  0_0402_5%  [R0402_0OHM]  302.77 25.59 90 top
RE38  0_0402_5%  [R_0402]  297.56 5.04 270 top
RE39  0_0402_5%  [R0402_0OHM]  297.82 6.54 90 top
RE41  100K_0402_5%  [R_0402]  308.1 10.98 90 top
RE43  1K_0402_5%  [R_0402]  287.91 15.81 90 top
RE44  100K_0402_5%  [R_0402]  288.93 15.81 90 top
RE45  10_0402_5%  [R_0402]  307.21 10.98 90 top
RE48  33_0402_5%  [R_0402]  293.12 23.3 90 top
RE50  100K_0402_5%  [R_0402]  287.53 14.94 270 top
RE51  0_0402_5%  [R0402_0OHM]  291.16 10.55 180 top
RE52  10K_0402_5%  [R_0402]  309.25 13.9 90 top
RE54  10K_0402_5%  [R_0402]  286.64 14.03 90 top
RE55  4.7K_0402_5%  [R_0402]  287.61 18.06 180 top
RE56  100K_0402_5%  [R_0402]  310.11 12.77 0 top
RE57  1K_0402_5%  [R_0402]  309.07 16.14 180 top
RE58  1.5K_0402_1%  [R_0402]  306.3 9.19 0 top
RE59  100K_0402_5%  [R_0402]  298.02 26.68 180 top
RE60  49.9_0402_1%  [R_0402]  312.99 27.75 90 top
RE61  100_0402_1%  [R_0402]  297.1 24.39 0 top
RE62  10_0402_5%  [R_0402]  306.38 17.66 0 top
RE63  10K_0402_5%  [R_0402]  309.06 27.75 90 top
RE64  10K_0402_5%  [R_0402]  307.02 27.75 90 top
RE65  100K_0402_5%  [R_0402]  308.17 27.75 90 top
RE66  8.2K_0402_5%  [R_0402]  307.34 18.98 90 top
RE67  4.3K_0402_5%  [R_0402]  300.56 7.37 180 top
RE68  10K_0402_5%  [R_0402]  287.66 7.93 90 top
RE69  2.2K_0402_5%  [R_0402]  311.66 19.9 270 top
RE70  10K_0402_5%  [R_0402]  285.87 8.84 0 top
RE71  100K_0402_5%  [R_0402]  272.21 16.26 0 top
RE72  100K_0402_5%  [R_0402]  272.21 15.25 0 top
RE73  10K_0402_5%  [R_0402]  283.54 13.72 180 top
RE74  10K_0402_5%  [R_0402]  283.54 14.74 180 top
RE75  10K_0402_5%  [R_0402]  283.54 15.76 180 top
RE76  10K_0402_5%  [R_0402]  283.54 16.9 180 top
RE77  4.7K_0402_5%  [R_0402]  154.23 3.06 0 top
RE81  100K_0402_5%  [R_0402]  101.28 35.72 270 top
RE82  10K_0402_5%  [R_0402]  98.17 34.06 90 top
RE83  100K_0402_5%  [R_0402]  321.88 36.64 90 top
RE84  10K_0402_5%  [R_0402]  321.57 40.15 270 top
RE85  10K_0402_5%  [R_0402]  152.45 2.99 0 top
RE86  10K_0402_5%  [R_0402]  149.14 11.36 0 top
RE87  100K_0402_5%  [R_0402]  189 10.25 180 top
RE89  10K_0402_5%  [R_0402]  289.94 5.04 270 top
RE90  100K_0402_5%  [R_0402]  290.83 4.12 90 top
RE93  0_0603_5%  [R0603_0OHM]  191.66 8.98 180 top
RE94  2.2K_0402_5%  [R_0402]  298.64 30.67 90 top
RE95  2.2K_0402_5%  [R_0402]  296.28 32.46 0 top
RE96  100_0402_5%  [R_0402]  295.78 23.3 90 top
RE99  10K_0402_5%  [R_0402]  299.09 25.59 90 top
RE100  10K_0402_5%  [R_0402]  98.08 32.95 0 top
RE101  10K_0402_5%  [R_0402]  320.49 39.24 90 top
RE102  0_0402_5%  [R0402_0OHM]  299.98 26.5 270 top
RE103  0_0402_5%  [R0402_0OHM]  304.42 28.91 270 top
RE104  0_0603_5%  [R0603_0OHM]  97.03 34.07 90 top
RE105  0_0603_5%  [R0603_0OHM]  320.8 41.91 0 top
RE107  0_0402_5%  [R0402_0OHM]  291.16 21.04 270 top
RE108  0_0402_5%  [R0402_0OHM]  296.61 5.1 270 top
RE109  0_0402_5%  [R0402_0OHM]  295.72 5.1 270 top
RE110  10K_0402_5%  [R_0402]  282.58 4.71 270 top
RE111  43K_0402_1%  [R_0402]  292.18 23.33 90 top
RE112  0_0402_5%  [R0402_0OHM]  299.4 5.04 270 top
RE113  33_0402_5%  [R_0402]  151.19 2.42 90 top
RE114  33_0402_5%  [R_0402]  149.28 6.65 0 top
RE115  33_0402_5%  [R_0402]  149.29 8.63 270 top
RE116  0_0402_5%  [R0402_0OHM]  153.47 8.15 0 bottom
RE117  0_0402_5%  [R0402_0OHM]  152.59 11.45 0 bottom
RE118  0_0402_5%  [R0402_0OHM]  299.98 24.22 270 top
RE119  0_0402_5%  [R0402_0OHM]  303.53 28.91 270 top
RE120  0_0402_5%  [R0402_0OHM]  303.61 3.82 180 top
RE121  0_0603_5%  [R0603_0OHM]  148.97 13.66 270 top
RE122  0_0402_5%  [R0402_0OHM]  300.15 30.11 0 top
RE125  0_0402_5%  [R_0402]  156.92 3.06 180 top
RE126  0_0402_5%  [R_0402]  155.53 11.31 180 top
RE128  0_0402_5%  [R_0402]  156.77 11.57 0 top
RE129  0_0402_5%  [R0402_0OHM]  159.46 11.57 180 top
RE133  0_0402_5%  [R0402_0OHM]  148.34 8.59 270 top
RE134  10K_0402_5%  [R_0402]  155.53 12.2 180 top
RE136  5.1K_0402_1%  [R_0402]  67.9 20.46 180 bottom
RE137  5.1K_0402_1%  [R_0402]  67.74 16.65 0 bottom
RE138  0_0402_5%  [R0402_0OHM]  306.02 25.66 180 top
RE139  0_0402_5%  [R0402_0OHM]  300.86 4.76 90 top
RE140  10K_0402_5%  [R_0402]  285.87 7.95 0 top
RE141  0_0603_5%  [R0603_0OHM]  152.15 5.09 0 bottom
RE142  100K_0402_5%  [R_0402]  308.12 10.03 0 top
RE143  100K_0402_5%  [R_0402]  272.6 9.66 0 top
RE144  0_0402_5%  [R_0402]  158.37 2.6 90 top
RF1  0_0603_5%  [R0603_0OHM]  241.66 44.47 90 top
RF2  100K_0402_5%  [R_0402]  232.93 43.44 270 top
RF3  100K_0402_5%  [R_0402]  238.44 44.41 270 top
RF4  100K_0402_5%  [R_0402]  238.34 45.73 180 top
RF5  100K_0402_5%  [R_0402]  239.33 44.41 270 top
RH2  1K_0402_5%  [R_0402]  132.92 94.56 180 bottom
RH5  1K_0402_5%  [R_0402]  123.57 94.55 90 bottom
RH6  0_0402_5%  [R_0402]  132 95.45 0 bottom
RH8  0_0402_5%  [R0402_0OHM]  124.46 95.46 270 bottom
RH12  0_0402_5%  [R0402_0OHM]  119.19 95.4 270 bottom
RH24  24.9_0402_1%  [R_0402]  173.79 54.87 0 bottom
RH30  24.9_0402_1%  [R_0402]  177.14 86.39 90 top
RH57  49.9_0402_1%  [R_0402]  131.79 75.92 0 bottom
RH58  49.9_0402_1%  [R_0402]  131.79 77.7 0 bottom
RH59  49.9_0402_1%  [R_0402]  132.7 76.81 180 bottom
RH67  1.3K_0402_5%  [R_0402]  349.19 84.67 270 top
RH70  10M_0402_5%  [R_0402]  97.92 2.69 270 top
RH71  2.7K_0402_1%  [R_0402]  102.68 23.05 90 bottom
RH72  1M_0201_5%  [R_0201]  102.36 26.76 270 top
RH74  3.3K_0402_5%  [R_0402]  64.44 11.06 0 bottom
RH75  1K_0402_5%  [R_0402]  79.57 2.74 0 top
RH77  100K_0402_5%  [R_0402]  60.68 10.82 0 top
RH78  1K_0402_5%  [R_0402]  73.2 2.17 0 top
RH82  4.7K_0402_5%  [R_0402]  73.2 3.12 0 top
RH83  20K_0402_5%  [R_0402]  94.11 4.33 180 top
RH84  20K_0402_5%  [R_0402]  96.2 4.34 0 top
RH85  8.2K_0402_5%  [R_0402]  106.11 7.26 270 top
RH88  47K_0402_5%  [R_0402]  95.73 8.54 180 top
RH91  100K_0402_5%  [R_0402]  105.67 2.47 90 bottom
RH95  51_0402_5%  [R_0402]  103.65 10.17 180 top
RH96  0_0402_5%  [R0402_0OHM]  109.93 3.44 180 top
RH97  51_0402_5%  [R_0402]  108.85 9.27 180 top
RH98  51_0402_5%  [R_0402]  109.72 9.27 0 top
RH100  51_0402_5%  [R_0402]  108.85 7.88 180 bottom
RH108  100_0402_1%  [R_0402]  90.78 28.81 180 bottom
RH109  113_0402_1%  [R_0402]  101.87 14.41 0 bottom
RH110  10K_0402_5%  [R_0402]  76.02 12.58 180 top
RH111  10K_0402_5%  [R_0402]  67.68 10.13 0 top
RH119  4.7K_0402_5%  [R_0402]  68.66 14.23 180 top
RH120  4.7K_0402_5%  [R_0402]  70.94 10.66 180 bottom
RH130  4.7K_0402_5%  [R_0402]  84.71 11.07 270 top
RH133  0_0402_5%  [R0402_0OHM]  96.28 10.49 180 top
RH136  0_0603_5%  [R0603_0OHM]  79.44 4.2 180 top
RH137  0_0603_5%  [R0603_0OHM]  83.44 4.2 0 top
RH145  20_0402_5%  [R_0402]  180.65 80.22 315 bottom
RH146  30_0402_5%  [R_0402]  108.18 11.52 180 bottom
RH147  30_0402_5%  [R_0402]  108.37 10.36 180 bottom
RH148  121_0402_1%  [R_0402]  173.79 55.76 0 bottom
RH149  75_0402_1%  [R_0402]  173.79 56.65 0 bottom
RH150  100_0402_1%  [R_0402]  171.58 55.51 0 bottom
RH151  100_0402_5%  [R_0402]  132.8 103.01 270 top
RH152  56.2_0402_1%  [R_0402]  132.8 103.88 90 top
RH153  220_0402_5%  [R_0402]  133.69 104.8 270 top
RH154  60.4_0402_1%  [R_0402]  178.04 66.59 90 top
RH155  20_0402_5%  [R_0402]  130.15 82.94 0 bottom
RH156  51_0402_5%  [R_0402]  131.56 78.8 90 bottom
RH158  499_0402_1%  [R_0402]  130.15 80.84 0 bottom
RH163  1K_0402_5%  [R_0402]  173.03 81.53 180 top
RH164  1K_0402_5%  [R_0402]  179.75 64.77 90 top
RH165  1K_0402_5%  [R_0402]  129.78 78.8 90 bottom
RH166  49.9_0402_1%  [R_0402]  132.49 79.16 0 bottom
RH167  30_0402_5%  [R_0402]  181.42 62.29 90 top
RH168  22_0402_5%  [R_0402]  104.97 4.92 0 bottom
RH183  1K_0402_5%  [R_0402]  131.93 76.74 90 top
RH184  1K_0402_5%  [R_0402]  132.79 77.29 90 top
RH185  1K_0402_5%  [R_0402]  133.87 74.81 180 top
RH186  1K_0402_5%  [R_0402]  132.93 71.12 180 top
RH187  1K_0402_5%  [R_0402]  132.06 73.9 90 top
RH188  1K_0402_5%  [R_0402]  134 72.84 180 top
RH189  30_0402_5%  [R_0402]  104.75 13.48 90 bottom
RH190  0_0402_5%  [R0402_0OHM]  132.94 83.57 0 bottom
RH191  620_0402_5%  [R_0402]  103.66 14.26 90 bottom
RH192  30_0402_5%  [R_0402]  178.64 75.9 180 top
RH196  0_0402_5%  [R_0402]  87.9 10.79 270 top
RH197  100_0402_1%  [R_0402]  157.49 93.07 180 bottom
RH198  0_0402_5%  [R0402_0OHM]  155.65 93.07 180 bottom
RH201  100_0402_1%  [R_0402]  178.14 90.48 270 bottom
RH202  0_0402_5%  [R0402_0OHM]  178.19 91.72 90 bottom
RH203  100_0402_1%  [R_0402]  157.49 88.81 180 bottom
RH204  0_0402_5%  [R0402_0OHM]  155.65 88.81 180 bottom
RH206  1K_0402_1%  [R_0402]  124.84 19.24 270 top
RH207  1K_0402_1%  [R_0402]  233.15 19.39 270 top
RH209  1K_0402_1%  [R_0402]  123.81 18.32 270 top
RH210  1K_0402_1%  [R_0402]  233.15 17.61 270 top
RH211  24.9_0402_1%  [R_0402]  121.1 18.32 90 top
RH212  24.9_0402_1%  [R_0402]  231.42 17.42 270 top
RH309  0_0402_5%  [R0402_0OHM]  100.41 9.81 180 top
RH383  10K_0402_5%  [R_0402]  75.11 9.91 0 top
RH401  100K_0402_5%  [R_0402]  98.87 8.64 270 top
RH423  100K_0402_5%  [R_0402]  61.48 3.5 180 top
RH424  5.1K_0402_1%  [R_0402]  71.87 8.84 0 top
RH425  5.1K_0402_1%  [R_0402]  71.87 9.72 0 top
RH428  22_0402_5%  [R_0402]  105.33 5.85 0 bottom
RH453  1K_0402_5%  [R_0402]  109.02 4.33 0 top
RH454  1K_0402_5%  [R_0402]  115.75 5.62 180 top
RH455  1K_0402_5%  [R_0402]  77.28 2.27 180 top
RH456  0_0402_5%  [R_0402]  181.24 86.22 90 bottom
RH458  1K_0402_5%  [R_0402]  76.34 6.77 180 top
RH459  1K_0402_5%  [R_0402]  70.92 4.63 90 top
RH460  1K_0402_5%  [R_0402]  79.24 7.63 180 top
RH461  1K_0402_5%  [R_0402]  77.47 6.16 90 top
RH462  1K_0402_5%  [R_0402]  75.44 5.93 270 top
RH463  1K_0402_5%  [R_0402]  71.58 7.57 180 top
RH465  0_0402_5%  [R0402_0OHM]  155.65 91.61 180 bottom
RH466  100_0402_1%  [R_0402]  156.57 91.61 0 bottom
RH469  100_0402_1%  [R_0402]  176.86 90.48 270 bottom
RH470  0_0402_5%  [R0402_0OHM]  176.86 91.72 90 bottom
RH471  0_0402_5%  [R0402_0OHM]  155.65 90.27 180 bottom
RH472  100_0402_1%  [R_0402]  156.58 90.27 0 bottom
RH473  0_0402_5%  [R0402_0OHM]  164.13 68.16 270 top
RH474  1K_0402_5%  [R_0402]  130.15 84.84 0 bottom
RH475  0_0402_5%  [R_0402]  128.83 84.79 270 bottom
RH477  0_0402_5%  [R0402_0OHM]  118.3 95.4 270 bottom
RH478  0_0402_5%  [R0402_0OHM]  120.14 95.4 270 bottom
RH479  0_0402_5%  [R_0402]  119.19 94.38 180 top
RH480  1K_0402_5%  [R_0402]  119.19 93.49 180 top
RH481  1K_0402_5%  [R_0402]  130.47 92.74 270 top
RH482  1K_0402_5%  [R_0402]  130.47 90.05 90 top
RH483  150_0402_5%  [R_0402]  130.46 98.21 270 top
RH484  2_0402_1%  [R_0402]  122.89 19.24 270 top
RH485  2_0402_1%  [R_0402]  232.2 19.39 270 top
RH487  0_0402_5%  [R0402_0OHM]  116.7 5.52 0 top
RH488  1K_0402_5%  [R_0402]  130.47 96.43 270 top
RH489  1K_0402_5%  [R_0402]  70.52 3.45 0 bottom
RH490  0_0402_5%  [R_0402]  127.69 93.8 0 bottom
RH491  0_0402_5%  [R0402_0OHM]  131.89 102.09 90 top
RH492  2.2K_0402_5%  [R_0402]  119.19 95.4 180 top
RH493  2.2K_0402_5%  [R_0402]  127.69 94.71 0 bottom
RH494  51_0402_5%  [R_0402]  131.7 97.75 270 bottom
RH495  51_0402_5%  [R_0402]  134.62 97.75 270 bottom
RH496  51_0402_5%  [R_0402]  133.67 97.75 270 bottom
RH497  51_0402_5%  [R_0402]  130.15 81.92 0 bottom
RH498  51_0402_5%  [R_0402]  131.89 104.8 270 top
RH501  499_0402_1%  [R_0402]  70.54 7.77 0 bottom
RH502  499_0402_1%  [R_0402]  70.54 6.88 0 bottom
RH503  4.7K_0402_5%  [R_0402]  81.6 7.73 0 top
RH504  150K_0402_5%  [R_0402]  85.61 11.07 270 top
RH505  4.7K_0402_5%  [R_0402]  81.71 4.63 90 top
RH506  1M_0402_5%  [R_0402]  74.12 4.01 180 top
RH508  10K_0402_5%  [R_0402]  76.02 14.5 180 top
RH510  10K_0402_5%  [R_0402]  72.78 13.15 180 bottom
RH511  10K_0402_5%  [R_0402]  72.09 20.2 180 bottom
RH512  10K_0402_5%  [R_0402]  70.88 14.17 180 bottom
RH513  10K_0402_5%  [R_0402]  76.02 13.61 180 top
RH515  8.2K_0402_5%  [R_0402]  109.02 2.55 0 bottom
RH516  10K_0402_5%  [R_0402]  75.11 10.8 0 top
RH518  10K_0402_5%  [R_0402]  93.14 11.88 0 top
RH519  0_0402_5%  [R_0402]  130.15 83.96 0 bottom
RH520  100K_0402_5%  [R_0402]  75.11 9.03 0 top
RH521  0_0402_5%  [R_0402]  71.87 8.71 0 bottom
RH522  0_0402_5%  [R_0402]  71.87 9.6 0 bottom
RH523  10K_0402_5%  [R_0402]  71.87 10.61 0 bottom
RH524  4.7K_0402_5%  [R_0402]  82.36 3.51 270 top
RH525  220K_0402_5%  [R_0402]  121.36 54.24 180 top
RH527  10K_0402_5%  [R_0402]  82.82 17.92 180 top
RH528  10K_0402_5%  [R_0402]  83.74 17.92 0 top
RH529  100K_0402_5%  [R_0402]  108.71 7.64 270 top
RH530  0_0402_5%  [R_0402]  165.85 67.24 90 top
RH531  330K_0402_5%  [R_0402]  95.25 4.07 90 top
RH533  8.2K_0402_5%  [R_0402]  109.02 1.66 0 bottom
RH535  10K_0402_5%  [R_0402]  76.72 19.12 180 top
RH536  1K_0402_5%  [R_0402]  113.98 6.37 270 top
RH537  10K_0402_5%  [R_0402]  70.88 11.88 180 bottom
RH538  10K_0402_5%  [R_0402]  71.87 11.88 0 bottom
RH539  13_0402_5%  [R_0402]  102.5 11.91 0 bottom
RH540  0_0402_5%  [R0402_0OHM]  132.78 97.75 270 bottom
RH541  0_0402_5%  [R0402_0OHM]  135.51 97.75 270 bottom
RH542  0_0402_5%  [R0402_0OHM]  130.54 94.59 90 bottom
RH543  0_0402_5%  [R0402_0OHM]  128.89 82.32 270 bottom
RH544  10K_0402_5%  [R_0402]  109.02 5.28 0 top
RH545  10K_0402_5%  [R_0402]  112.95 5.53 0 bottom
RH546  10K_0402_5%  [R_0402]  82.92 10.3 0 top
RH547  10K_0402_5%  [R_0402]  70.54 4.63 0 bottom
RH548  10K_0402_5%  [R_0402]  71.45 2.46 180 bottom
RH549  10K_0402_5%  [R_0402]  71.45 5.52 180 bottom
RH550  10K_0402_5%  [R_0402]  70.94 10.63 180 top
RH551  10K_0402_5%  [R_0402]  69.97 11.88 0 top
RH552  10K_0402_5%  [R_0402]  70.88 13.15 180 bottom
RH553  10K_0402_5%  [R_0402]  69.97 15.44 0 bottom
RH554  10K_0402_5%  [R_0402]  76.02 15.38 180 top
RH555  10K_0402_5%  [R_0402]  72.72 15.44 180 bottom
RH556  10K_0402_5%  [R_0402]  70.09 8.78 0 bottom
RH557  10K_0402_5%  [R_0402]  59.17 6.87 270 top
RH558  10K_0402_5%  [R_0402]  91.19 4.23 90 top
RH561  49.9K_0402_1%  [R_0402]  68.11 11.5 180 top
RH562  49.9K_0402_1%  [R_0402]  68.11 12.52 180 top
RH563  10K_0402_5%  [R_0402]  75.11 8.07 0 top
RH564  100K_0402_5%  [R_0402]  79.55 6.42 0 top
RH565  100K_0402_5%  [R_0402]  81.33 6.42 0 top
RH566  100K_0402_5%  [R_0402]  80.07 7.87 90 top
RH567  100K_0402_5%  [R_0402]  78.82 8.54 180 top
RH568  100K_0402_5%  [R_0402]  60.39 2.47 90 bottom
RH569  100K_0402_5%  [R_0402]  61.41 2.47 90 bottom
RH570  49.9_0402_1%  [R_0402]  130.67 78.8 90 bottom
RH571  8.2K_0402_5%  [R_0402]  104.95 5.22 0 top
RH572  100K_0402_5%  [R_0402]  60.57 2.61 0 top
RH573  1K_0402_5%  [R_0402]  70 5.55 270 top
RH576  0_0402_5%  [R0402_0OHM]  60.57 4.96 0 top
RH577  0_0402_5%  [R0402_0OHM]  65.93 3.15 0 top
RH578  0_0402_5%  [R0402_0OHM]  66.33 2.27 0 top
RH579  0_0402_5%  [R0402_0OHM]  68.09 1.77 0 top
RH580  0_0402_5%  [R0402_0OHM]  95.51 14.36 90 top
RH581  0_0402_5%  [R0402_0OHM]  98.98 12.45 180 top
RH582  0_0603_5%  [R0603_0OHM]  81.98 31 180 top
RH583  0_0603_5%  [R0603_0OHM]  105.92 15.12 270 top
RH584  0_0603_5%  [R0603_0OHM]  101.83 15.38 0 top
RH585  0_0603_5%  [R0603_0OHM]  60.33 7.31 270 top
RH586  0_0402_5%  [R0402_0OHM]  66.22 12.84 0 bottom
RH587  0_0402_5%  [R_0402]  66.22 11.88 0 bottom
RH588  100K_0402_5%  [R_0402]  67.62 14.23 0 bottom
RH589  10K_0402_5%  [R_0402]  66.69 14.23 180 bottom
RH590  200_0402_5%  [R_0402]  346.15 88.52 180 top
RI4  100K_0402_5%  [R_0402]  28.26 92.1 270 top
RI5  100K_0402_5%  [R_0402]  28.32 88.96 90 top
RI6  33K_0402_1%  [R_0402]  22.3 90.43 180 top
RI7  22.1K_0402_1%  [R_0402]  22.3 89.42 180 top
RI8  10K_0402_5%  [R_0402]  27.64 82.46 180 top
RI9  100K_0402_5%  [R_0402]  329.06 54.61 90 bottom
RI10  100K_0402_5%  [R_0402]  329.06 53.74 270 bottom
RI11  33K_0402_1%  [R_0402]  337.3 62.43 0 bottom
RI12  22.1K_0402_1%  [R_0402]  337.3 61.54 0 bottom
RI13  10K_0402_5%  [R_0402]  325.76 49.09 0 top
RI14  0.01_0805_1%  [R_0805]  325.21 35.63 180 bottom
RI15  10K_0402_5%  [R_0402]  323.33 30.68 0 bottom
RI16  0_0402_5%  [R_0402]  323.33 32.46 0 bottom
RI17  10K_0402_5%  [R_0402]  315.93 30.87 180 bottom
RI18  0_0402_5%  [R_0402]  315.93 32.65 180 bottom
RI19  4.7K_0402_5%  [R_0402]  323.33 31.57 0 bottom
RI20  4.7K_0402_5%  [R_0402]  323.33 29.79 0 bottom
RI21  4.7K_0402_5%  [R_0402]  315.93 31.76 180 bottom
RI22  4.7K_0402_5%  [R_0402]  315.66 35.75 90 bottom
RI23  4.99K_0402_1%  [R_0402]  317.76 36.13 90 bottom
RI24  4.7K_0402_5%  [R_0402]  323.33 33.35 0 bottom
RI25  0_0402_5%  [R0402_0OHM]  317.5 28.66 270 bottom
RI26  1M_0402_5%  [R_0402]  27.43 86.67 90 top
RI27  1M_0402_5%  [R_0402]  325.78 53.48 90 top
RI28  0_0402_5%  [R_0402]  326.54 50.66 90 top
RI30  100K_0402_5%  [R_0402]  321.04 43 0 top
RI31  100K_0402_5%  [R_0402]  321.31 44 90 top
RI32  0_0402_5%  [R0402_0OHM]  323.72 47.37 90 top
RI33  0_0402_5%  [R0402_0OHM]  322.45 47.37 90 top
RI34  0_0402_5%  [R_0402]  323.55 46.43 180 top
RI35  0_0402_5%  [R_0402]  324.74 44 90 top
RI36  0_0402_5%  [R0402_0OHM]  316.92 34.17 0 top
RI37  0_0402_5%  [R0402_0OHM]  332.11 68.77 90 top
RI38  0_0402_5%  [R0402_0OHM]  333.12 68.77 90 top
RI39  0_0402_5%  [R0402_0OHM]  332.23 75.52 270 top
RI40  0_0402_5%  [R0402_0OHM]  333.19 75.52 270 top
RI41  0_0402_5%  [R0402_0OHM]  20 105.37 270 top
RI42  0_0402_5%  [R0402_0OHM]  19.11 105.37 270 top
RI43  0_0402_5%  [R0402_0OHM]  20 98.8 90 top
RI44  0_0402_5%  [R0402_0OHM]  19.11 98.8 90 top
RI45  0.01_0805_1%  [R_0805]  324.38 29.53 90 top
RI46  10K_0402_5%  [R_0402]  316.7 38.23 0 top
RL1  820_0402_5%  [R_0402]  344.22 101.35 0 top
RL2  820_0402_5%  [R_0402]  344.22 102.37 0 top
